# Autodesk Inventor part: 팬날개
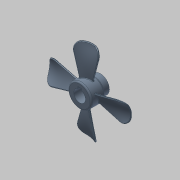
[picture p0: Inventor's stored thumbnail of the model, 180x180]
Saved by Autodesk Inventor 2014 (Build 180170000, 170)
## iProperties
Company: 한국ATC센터
Created: 2016-06
Part Number: 팬날개
Document SubType Name: Modeling
Designer: mdu
Density: 1.06 g/cm^3
Material: ABS 플라스틱
Mass: 26.2496 g
Surface Area: 149.78 cm^2
Volume: 24.7638 cm^3
Appearance: 강청색
Author: mdu
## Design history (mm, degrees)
sketch "스케치1"
  geometry: L1 (-15, 0)-(15, 0); L2 (-15, 0)-(-15, 17); L3 (-15, 17)-(5, 17); L4 (5, 17)-(5, 13); L5 (5, 13)-(15, 13); L6 (15, 13)-(15, 0); 2 further points
  constraints: 12 end point, 3 parallel, 2 perpendicular, 1 coincident, 1 horizontal, 1 midpoint
  dimensions: "d0" = 30 distance of L1.start L1.end; "d8" = 34 diameter of L3 L1; "d10" = 26 diameter of L5 L1; "d32" = 20 distance of L2.end L3.end
revolve "회전1" sketch "스케치1" stored, may be unused: angle "d11" = 90 deg
node "작업 평면2"
sketch "스케치7"
  geometry: L1 (-15, 17)-(5, 17) reference; L2 (-15, -17)-(5, -17) reference; L3 (-5, 17)-(-5, -17); A1 r 35 centre (-36.399, -13.457) between (-2, -7) and (-8, 7); 1 further point
  constraints: 2 end point, 2 midpoint, 2 point on circle, 1 centre point
  dimensions: "d36" = 35 radius of A1; "d37" = 10 distance from line of A1.start L2; "d38" = 10 distance from line of A1.end L1; "d45" = 3 distance from line of A1.end L3; "d46" = 3 distance from line of A1.start L3
sketch "3D 스케치1"
  geometry: L1 through (0, 0) direction (1, 0) reference; L2 through (0, 0) direction (1, 0) reference; 13 other entities
  constraints: 2 collinear
  node "투영 원본 위치 스케치7"
sketch "스케치8"
  geometry: L1 (-15, 17)-(5, 17) reference; L2 (-15, -17)-(5, -17) reference; L3 (-5, 17)-(-5, -17); A1 r 30 centre (-28.74, -3.591) between (-3, -19) and (-9, 19); 1 further point
  constraints: 2 end point, 2 midpoint, 2 point on circle, 1 centre point
  dimensions: "d43" = 30 radius of A1; "d47" = 4 distance from line of A1.end L3; "d48" = 2 distance from line of A1.start L3; "d58" = 2 distance from line of A1.end L1; "d59" = 2 distance from line of A1.start L2
sketch "3D 스케치2"
sketch "3D 스케치3"
feature "경계 패치1" sketch "3D 스케치2", "3D 스케치3" dims "d50" = 0
feature "연장1" dims "d55" = 2
feature "두껍게 하기1" dims "d51" = 2, "d52" = 2
sketch "스케치9"
  geometry: C1 r 59 at (0, 0); 1 further point
  constraints: 1 centre point, 1 coincident
  dimensions: "d60" = 118 diameter of C1
extrude "돌출2" sketch "스케치9" distance "d62" = 200; taper "d63" = 0 deg
fillet "모깎기6" dims "d64" = 10
fillet "모깎기7" dims "d66" = 0.8
fillet "모깎기8" dims "d67" = 0.8
sketch "스케치2"
  geometry: L1 (-2.5, 8.124)-(-2.5, 10.8); L2 (-2.5, 10.8)-(2.5, 10.8); L3 (2.5, 10.8)-(2.5, 8.124); A1 r 8.5 centre (0, 0) between (-2.5, 8.124) and (2.5, 8.124); 1 further point
  constraints: 6 end point, 2 parallel, 2 point on circle, 1 centre point, 1 coincident, 1 horizontal, 1 vertical
  dimensions: "d12" = 17 diameter of A1; "d13" = 5 distance of L1.end L2.end; "d14" = 19.3 dimension on A1 L2 (computed from d12)
extrude "돌출1" cut sketch "스케치2" stored distance "d15" = 10; taper "d16" = 0 deg
chamfer "모따기1" distance "d17" = 1; stored, may be unused: second distance "d18" = 2, angle "d19" = 45 deg
node "작업 평면1"
sketch "스케치3"
  geometry: L1 (5, -13)-(5, 13) reference; 3 further points
  constraints: 1 horizontal alignment, 1 midpoint
  dimensions: "d20" = 5 distance from line of L1 point (0, 0)
hole "구멍1" sketch "스케치3" at (0, 0) diameter "d21" = 3.242; stored, may be unused: countersink angle "d25" = 90 deg, drill point angle "d27" = 118 deg; dims "d22" = 6, "d23" = 4, "d24" = 2, "d26" = 8
fillet "모깎기9" dims "d77" = 2
fillet "모깎기10" dims "d78" = 2
fillet "모깎기11" dims "d79" = 2
node "솔리드1"
pattern_circular "원형 패턴1" dims "d69" = 360 deg
pattern_circular "원형 패턴2" dims angle "d72" = 360 deg
pattern_circular "원형 패턴3" dims angle "d75" = 360 deg
node "투영 원본 위치 스케치8"
node "곡면1"
node "곡면2"
node "곡면3"
node "곡면4"
feature "경계 패치2"
feature "경계 패치3"
feature "경계 패치4"
